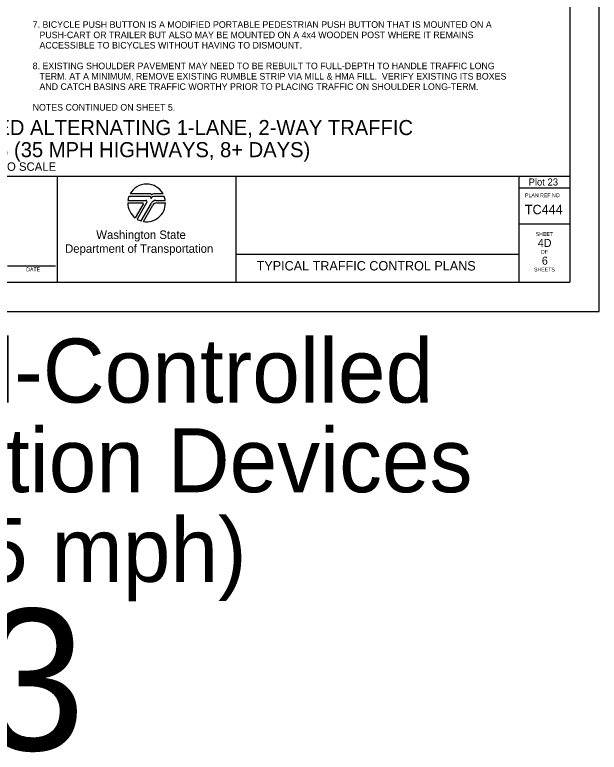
# Model space of a CAD drawing. Extents: x 99976 to 100136, y 99905 to 100011.
# Drawn here: x 100049.86 to 100056.06, y 99935.01 to 99942.84 of the extents above; entities that cross this region are included whole.
import ezdxf

# ---------------------------------------------------------------- set-up
doc = ezdxf.new("R2010")
doc.units = 0
for name, color, linetype in [('SH_DE_DetailHeading1Text', 7, 'Continuous'), ('SH_GI_GeneralNotesBodyText', 7, 'Continuous'), ('SH_GI_PlotLimits', 7, 'Continuous'), ('SH_GI_SheetBorder', 7, 'Continuous'), ('SH_GI_SheetLocationText', 7, 'Continuous'), ('SH_GI_SheetTextInCells', 7, 'Continuous'), ('SH_GI_TitleBlockText', 7, 'Continuous'), ('SH_GI_WSDOTLogo', 7, 'Continuous')]:
    doc.layers.add(name, color=color, linetype=linetype)

msp = doc.modelspace()

# ---------------------------------------------------------------- linework, layer by layer
at = {"layer": 'SH_GI_PlotLimits'}
msp.add_lwpolyline([(100039.0625, 99939.6875), (100056.0625, 99939.6875), (100056.0625, 99950.6875), (100039.0625, 99950.6875)], close=True, dxfattribs=at)
at = {"layer": 'SH_GI_SheetBorder'}
for p, q in [((100055.75, 99950.375), (100055.75, 99940)), ((100040, 99941.1259), (100055.75, 99941.1259)), ((100050.3089, 99941.1259), (100050.3089, 99940)), ((100052.2055, 99941.1259), (100052.2055, 99940)), ((100055.2079, 99941.1259), (100055.2079, 99940)), ((100055.2079, 99941.0008), (100055.75, 99941.0008)), ((100055.2079, 99940.6176), (100055.75, 99940.6176)), ((100052.2055, 99940.2955), (100055.2079, 99940.2955)), ((100049.7797, 99940.1733), (100050.2914, 99940.1733)), ((100040, 99940), (100055.75, 99940))]:
    msp.add_line(p, q, dxfattribs=at)
at = {"layer": 'SH_GI_WSDOTLogo'}
for p, q in [((100051.2894, 99940.9094), (100051.0697, 99940.9094)), ((100051.303, 99940.9354), (100051.0815, 99940.9354)), ((100051.433, 99940.9354), (100051.3351, 99940.9354)), ((100051.343, 99940.9094), (100051.3429, 99940.9094)), ((100051.4448, 99940.9094), (100051.343, 99940.9094)), ((100051.0572, 99940.84), (100051.2148, 99940.84)), ((100051.059, 99940.8661), (100051.2496, 99940.8661)), ((100051.222, 99940.8277), (100051.1364, 99940.6807)), ((100051.261, 99940.8464), (100051.1567, 99940.6672)), ((100051.1989, 99940.6487), (100051.3089, 99940.839)), ((100051.2244, 99940.6428), (100051.3242, 99940.8156)), ((100051.3558, 99940.8661), (100051.4555, 99940.8661)), ((100051.3655, 99940.8394), (100051.4572, 99940.8394))]:
    msp.add_line(p, q, dxfattribs=at)
for centre, radius, start, end in [((100051.2572, 99940.84), 0.2, 28.47865, 151.53204), ((100051.2572, 99940.84), 0.2, 159.69598, 172.50569), ((100051.2894, 99940.8946), 0.0148, 327.8418, 89.99855), ((100051.3429, 99940.861), 0.0484, 89.99529, 147.82376), ((100051.303, 99940.9263), 0.00903, 329.87418, 90.00328), ((100051.3352, 99940.9066), 0.0287, 90.00721, 148.16763), ((100051.2572, 99940.84), 0.2, 7.49431, 20.29406), ((100051.2572, 99940.84), 0.2, 179.99864, 232.84327), ((100051.2149, 99940.8318), 0.0082, 329.74356, 90), ((100051.2572, 99940.84), 0.2, 260.54554, 359.80857), ((100051.2497, 99940.853), 0.0131, 329.76834, 90), ((100051.3558, 99940.8119), 0.0542, 90, 149.99738), ((100051.3654, 99940.7918), 0.0476, 90, 150.05432), ((100051.2572, 99940.84), 0.2, 239.79292, 253.0448)]:
    msp.add_arc(centre, radius, start, end, dxfattribs=at)

# ---------------------------------------------------------------- texts
at = {"layer": 'SH_DE_DetailHeading1Text'}
for s, height, p in [('ADVANCED TEMPORARY SIGNAL-CONTROLLED ALTERNATING 1-LANE, 2-WAY TRAFFIC', 0.16, (100044.9788, 99941.5606)), ('35 WZSL + CHANNELIZING DEVICES (35 MPH HIGHWAYS, 8+ DAYS)', 0.16, (100046.0628, 99941.3259)), ('NOT TO SCALE', 0.09, (100049.4141, 99941.1809))]:
    msp.add_text(s, height=height, rotation=360, dxfattribs=at).set_placement(p)
at = {"layer": 'SH_GI_GeneralNotesBodyText'}
for s, p in [('7. BICYCLE PUSH BUTTON IS A MODIFIED PORTABLE PEDESTRIAN PUSH BUTTON THAT IS MOUNTED ON A ', (100050.0475, 99942.6998)), ('PUSH-CART OR TRAILER BUT ALSO MAY BE MOUNTED ON A 4x4 WOODEN POST WHERE IT REMAINS ', (100050.1197, 99942.5899)), ('ACCESSIBLE TO BICYCLES WITHOUT HAVING TO DISMOUNT.', (100050.1197, 99942.48)), ('8. EXISTING SHOULDER PAVEMENT MAY NEED TO BE REBUILT TO FULL-DEPTH TO HANDLE TRAFFIC LONG ', (100050.0475, 99942.2602)), ('TERM. AT A MINIMUM, REMOVE EXISTING RUMBLE STRIP VIA MILL & HMA FILL.  VERIFY EXISTING ITS BOXES ', (100050.1197, 99942.1503)), ('AND CATCH BASINS ARE TRAFFIC WORTHY PRIOR TO PLACING TRAFFIC ON SHOULDER LONG-TERM.', (100050.1197, 99942.0404)), ('NOTES CONTINUED ON SHEET 5.', (100050.0475, 99941.8206))]:
    msp.add_text(s, height=0.07, rotation=360, dxfattribs=at).set_placement(p)
at = {"layer": 'SH_GI_SheetBorder'}
msp.add_text('PLAN REF NO', height=0.040032, dxfattribs=at).set_placement((100055.2747, 99940.9008))
at = {"layer": 'SH_GI_SheetLocationText'}
for s, height, p in [('Plot 23', 0.075, (100055.3127, 99941.025)), (' Temp Signal-Controlled', 0.68, (100044.4951, 99938.7191)), ('Alt Traffic w/ Channelization Devices', 0.68, (100039.9592, 99937.7671)), ('& Rumble Strips (35 mph)', 0.68, (100041.8582, 99936.8151)), ('Plot 23', 1.5, (100044.3607, 99935.0267))]:
    msp.add_text(s, height=height, dxfattribs=at).set_placement(p)
at = {"layer": 'SH_GI_SheetTextInCells'}
for s, height, p in [('Washington State', 0.090072, (100050.7229, 99940.4571)), ('SHEET', 0.04003, (100055.3877, 99940.4896)), ('Department of Transportation', 0.090072, (100050.3916, 99940.3101)), ('OF', 0.04003, (100055.4406, 99940.3008)), ('DATE', 0.04003, (100049.9794, 99940.1141)), ('SHEETS', 0.04003, (100055.3698, 99940.112))]:
    msp.add_text(s, height=height, dxfattribs=at).set_placement(p)
at = {"layer": 'SH_GI_TitleBlockText'}
for s, height, p in [('TC444', 0.1, (100055.2728, 99940.72)), ('4D', 0.085, (100055.4101, 99940.3723)), ('6', 0.085, (100055.4534, 99940.1843)), ('TYPICAL TRAFFIC CONTROL PLANS', 0.1, (100052.4251, 99940.1224))]:
    msp.add_text(s, height=height, dxfattribs=at).set_placement(p)

doc.saveas('drawing.dxf')
